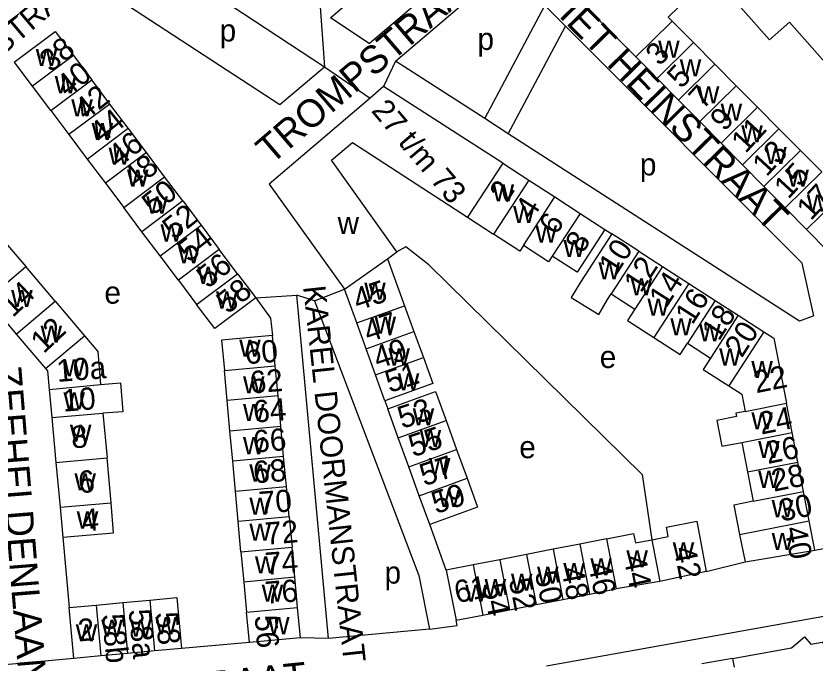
# Model space of a CAD drawing. Extents: x 159902 to 161769, y 383692 to 384875.
# Drawn here: x 160604.7 to 160748.2, y 384500.8 to 384617 of the extents above; entities that cross this region are included whole.
import ezdxf

# ---------------------------------------------------------------- set-up
doc = ezdxf.new("R2010")
doc.units = 0
for name, color, linetype in [('BLT_Basislijn', 7, 'Continuous'), ('BLT_Bebouwing', 7, 'Continuous'), ('BLT_Centroide', 7, 'Continuous'), ('BLT_Huisnummer', 7, 'Continuous'), ('BLT_Huisnummer_ tussenligend', 7, 'Continuous'), ('BLT_Huisnummer_reeks', 7, 'Continuous'), ('BLT_Onderverdeling_panden', 7, 'Continuous'), ('BLT_Straatnaam', 7, 'Continuous'), ('BLT_Straatnaam_verkleind', 7, 'Continuous'), ('BLT_Vlakafsluiter', 7, 'Continuous')]:
    doc.layers.add(name, color=color, linetype=linetype)

msp = doc.modelspace()

# ---------------------------------------------------------------- linework, layer by layer
at = {"layer": 'BLT_Basislijn'}
for p, q in [((160618.79, 384635.3), (160660.13, 384607.85)), ((160661.2, 384616.69), (160683.14, 384635.37)), ((160672.92, 384608.87), (160692.81, 384625.83)), ((160688.92, 384598.57), (160699.73, 384618.89)), ((160703.43, 384615.19), (160699.73, 384618.89)), ((160716.03, 384609.65), (160706.66, 384619.03)), ((160668.17, 384612.03), (160661.2, 384616.69)), ((160693.14, 384595.85), (160703.43, 384615.19)), ((160693.14, 384595.85), (160688.92, 384598.57)), ((160710.48, 384578.65), (160711.75, 384577.86)), ((160660.84, 384505.16), (160655.17, 384566.86)), ((160658.36, 384565.8), (160655.17, 384566.86)), ((160658.36, 384565.8), (160677.11, 384516.47)), ((160670.99, 384547.86), (160671.51, 384546.42)), ((160682.01, 384517.43), (160679.05, 384525.64)), ((160613.15, 384523.37), (160614.29, 384510.72)), ((160748.21, 384521.03), (160760.62, 384523.48)), ((160728.65, 384517.2), (160735.65, 384518.91)), ((160677.11, 384516.47), (160678.99, 384506.84)), ((160678.99, 384506.84), (160660.84, 384505.16)), ((160660.84, 384505.16), (160655.81, 384505.3)), ((160646.65, 384504.46), (160634.45, 384503.37))]:
    msp.add_line(p, q, dxfattribs=at)
for points in [[(160668.17, 384612.03), (160688.35, 384629.26)], [(160615.34, 384625.16), (160652.13, 384601.1), (160660.13, 384607.85)], [(160729.7, 384624.45), (160721.84, 384616.77), (160722.55, 384616.08)], [(160765.29, 384591.35), (160743.62, 384615.9), (160740.04, 384612.73), (160729.7, 384624.45)], [(160605.23, 384617.31), (160592.52, 384607.87), (160575.73, 384593.91)], [(160748.03, 384563.1), (160745.94, 384572.6), (160703.43, 384615.19)], [(160688.92, 384598.57), (160672.92, 384608.87)], [(160748.03, 384563.1), (160745.44, 384562.19), (160693.14, 384595.85)], [(160678.89, 384572.28), (160674.74, 384575.55), (160673.14, 384574.65)], [(160678.89, 384572.28), (160717.16, 384534.63), (160718.93, 384522.9)], [(160647.79, 384566.35), (160650.43, 384562.73), (160650.81, 384559.59)], [(160758.87, 384500), (160751.1, 384509.34), (160700, 384500.18)], [(160678.99, 384506.84), (160683.97, 384507.47), (160683.77, 384508.44)]]:
    msp.add_lwpolyline(points, dxfattribs=at)
at = {"layer": 'BLT_Bebouwing'}
for p, q in [((160722.55, 384616.08), (160719.09, 384612.66)), ((160726.38, 384612.22), (160722.55, 384616.08)), ((160611.79, 384614.23), (160615.06, 384609.88)), ((160719.09, 384612.66), (160716.03, 384609.65)), ((160730.22, 384608.34), (160726.38, 384612.22)), ((160615.06, 384609.88), (160618.34, 384605.53)), ((160607.72, 384604.36), (160604.61, 384608.5)), ((160716.03, 384609.65), (160719.86, 384605.77)), ((160734.07, 384604.47), (160730.22, 384608.34)), ((160621.61, 384601.18), (160618.34, 384605.53)), ((160719.86, 384605.77), (160723.7, 384601.89)), ((160611, 384600.01), (160607.72, 384604.36)), ((160670.75, 384604.32), (160668.34, 384602.26)), ((160692.14, 384590.55), (160670.75, 384604.32)), ((160737.91, 384600.6), (160734.07, 384604.47)), ((160624.88, 384596.82), (160621.61, 384601.18)), ((160668.34, 384602.26), (160650.23, 384586.8)), ((160723.7, 384601.89), (160727.53, 384598.01)), ((160611, 384600.01), (160614.24, 384595.69)), ((160741.75, 384596.73), (160737.91, 384600.6)), ((160628.16, 384592.47), (160624.88, 384596.82)), ((160727.53, 384598.01), (160731.37, 384594.13)), ((160614.24, 384595.69), (160617.54, 384591.3)), ((160745.59, 384592.85), (160741.75, 384596.73)), ((160731.37, 384594.13), (160735.21, 384590.26)), ((160749.43, 384588.98), (160745.59, 384592.85)), ((160617.54, 384591.3), (160620.82, 384586.95)), ((160631.43, 384588.12), (160628.16, 384592.47)), ((160692.14, 384590.55), (160696.81, 384587.52)), ((160735.21, 384590.26), (160739.04, 384586.38)), ((160620.82, 384586.95), (160624.09, 384582.6)), ((160634.7, 384583.76), (160631.43, 384588.12)), ((160650.23, 384586.8), (160663.73, 384567.92)), ((160696.81, 384587.52), (160701.49, 384584.48)), ((160739.04, 384586.38), (160742.88, 384582.5)), ((160701.49, 384584.48), (160706.03, 384581.54)), ((160627.37, 384578.24), (160624.09, 384582.6)), ((160634.7, 384583.76), (160637.98, 384579.41)), ((160742.88, 384582.5), (160746.71, 384578.62)), ((160685.83, 384580.84), (160690.51, 384577.8)), ((160630.64, 384573.89), (160627.37, 384578.24)), ((160637.98, 384579.41), (160641.25, 384575.06)), ((160746.71, 384578.62), (160750.55, 384574.74)), ((160716.57, 384574.76), (160711.75, 384577.86)), ((160603.24, 384575.84), (160606.51, 384571.97)), ((160633.91, 384569.54), (160630.64, 384573.89)), ((160644.52, 384570.7), (160641.25, 384575.06)), ((160716.57, 384574.76), (160720.83, 384572.01)), ((160611.8, 384565.75), (160606.51, 384571.97)), ((160720.83, 384572.01), (160725.55, 384568.96)), ((160644.52, 384570.7), (160647.79, 384566.35)), ((160633.91, 384569.54), (160637.19, 384565.18)), ((160725.55, 384568.96), (160730.27, 384565.91)), ((160611.8, 384565.75), (160617.07, 384559.56)), ((160730.27, 384565.91), (160734.42, 384563.23)), ((160674.52, 384564.95), (160676.21, 384560.29)), ((160734.42, 384563.23), (160739.02, 384560.26)), ((160602.74, 384562.26), (160604.79, 384559.83)), ((160667.62, 384557.17), (160665.93, 384561.84)), ((160604.79, 384559.83), (160610.05, 384553.64)), ((160651.31, 384554.15), (160650.81, 384559.59)), ((160676.21, 384560.29), (160677.9, 384555.62)), ((160739.02, 384560.26), (160740.82, 384559.11)), ((160725.3, 384558.21), (160729.45, 384555.53)), ((160740.82, 384559.11), (160743.09, 384547.41)), ((160669.31, 384552.51), (160667.62, 384557.17)), ((160651.81, 384548.73), (160651.31, 384554.15)), ((160610.05, 384553.64), (160610.39, 384553.24)), ((160610.39, 384553.24), (160610.7, 384549.87)), ((160642.66, 384547.89), (160642.16, 384553.31)), ((160610.7, 384549.87), (160611.17, 384544.85)), ((160652.31, 384543.3), (160651.81, 384548.73)), ((160643.16, 384542.46), (160642.66, 384547.89)), ((160744.11, 384542.14), (160743.09, 384547.41)), ((160620.37, 384545.62), (160621.1, 384537.64)), ((160673.4, 384541.22), (160671.51, 384546.42)), ((160611.17, 384544.85), (160611.92, 384536.77)), ((160681.99, 384544.34), (160683.87, 384539.14)), ((160643.66, 384537.03), (160643.16, 384542.46)), ((160652.81, 384537.87), (160652.31, 384543.3)), ((160675.28, 384536.02), (160673.4, 384541.22)), ((160745.14, 384536.86), (160744.11, 384542.14)), ((160735.07, 384540.37), (160736.1, 384535.09)), ((160683.87, 384539.14), (160685.76, 384533.94)), ((160611.92, 384536.77), (160612.68, 384528.75)), ((160621.83, 384529.52), (160621.1, 384537.64)), ((160644.15, 384531.6), (160643.66, 384537.03)), ((160653.31, 384532.44), (160652.81, 384537.87)), ((160746.17, 384531.58), (160745.14, 384536.86)), ((160677.17, 384530.82), (160675.28, 384536.02)), ((160736.1, 384535.09), (160737.13, 384529.81)), ((160653.81, 384527.01), (160653.31, 384532.44)), ((160644.65, 384526.17), (160644.15, 384531.6)), ((160747.19, 384526.3), (160746.17, 384531.58)), ((160612.68, 384528.75), (160613.15, 384523.37)), ((160653.81, 384527.01), (160654.31, 384521.58)), ((160645.15, 384520.74), (160644.65, 384526.17)), ((160748.21, 384521.03), (160747.19, 384526.3)), ((160734.68, 384523.85), (160735.65, 384518.91)), ((160710.78, 384523.07), (160705.99, 384522.13)), ((160654.81, 384516.16), (160654.31, 384521.58)), ((160701.19, 384521.19), (160696.4, 384520.25)), ((160705.99, 384522.13), (160701.19, 384521.19)), ((160735.65, 384518.91), (160748.21, 384521.03)), ((160645.15, 384520.74), (160645.65, 384515.31)), ((160696.4, 384520.25), (160691.6, 384519.31)), ((160691.6, 384519.31), (160686.81, 384518.37)), ((160645.65, 384515.31), (160646.15, 384509.89)), ((160655.31, 384510.73), (160654.81, 384516.16)), ((160720.38, 384515.38), (160712.54, 384514.06)), ((160707.75, 384513.12), (160712.54, 384514.06)), ((160698.16, 384511.25), (160702.96, 384512.19)), ((160702.96, 384512.19), (160707.75, 384513.12)), ((160614.29, 384510.72), (160619.12, 384511.17)), ((160619.12, 384511.17), (160623.95, 384511.61)), ((160623.95, 384511.61), (160628.77, 384512.06)), ((160655.81, 384505.3), (160655.31, 384510.73)), ((160693.37, 384510.31), (160698.16, 384511.25)), ((160615.14, 384501.58), (160614.29, 384510.72)), ((160646.65, 384504.46), (160646.15, 384509.89)), ((160688.57, 384509.38), (160693.37, 384510.31)), ((160655.81, 384505.3), (160646.65, 384504.46)), ((160624.8, 384502.47), (160619.97, 384502.03)), ((160629.62, 384502.92), (160624.8, 384502.47)), ((160634.45, 384503.37), (160629.62, 384502.92)), ((160619.97, 384502.03), (160615.14, 384501.58)), ((160733.41, 384501.57), (160727.9, 384500.58))]:
    msp.add_line(p, q, dxfattribs=at)
for points in [[(160604.61, 384608.5), (160604.45, 384608.71), (160611.79, 384614.23)], [(160673.14, 384574.65), (160661.4, 384591.1), (160665.18, 384594.28), (160685.83, 384580.84)], [(160706.03, 384581.54), (160710.48, 384578.65)], [(160710.48, 384578.65), (160705.49, 384570.96), (160701.04, 384573.84)], [(160695.85, 384575.78), (160695.85, 384575.78), (160695.19, 384574.77), (160690.51, 384577.8)], [(160711.75, 384577.86), (160711.75, 384577.86), (160706.13, 384569.15), (160704.45, 384566.42), (160709.38, 384563.38), (160710.94, 384566.04), (160711.59, 384567.05)], [(160701.04, 384573.84), (160700.39, 384572.84), (160695.85, 384575.78)], [(160671.46, 384573.39), (160673.14, 384574.65)], [(160671.46, 384573.39), (160674.52, 384564.95)], [(160665.93, 384561.84), (160663.73, 384567.92)], [(160711.59, 384567.05), (160711.59, 384567.05), (160715.85, 384564.3)], [(160647.79, 384566.35), (160640.46, 384560.83), (160637.19, 384565.18)], [(160715.85, 384564.3), (160714.55, 384562.29), (160719.27, 384559.24)], [(160617.07, 384559.56), (160619.45, 384556.73), (160619.94, 384550.81)], [(160650.81, 384559.59), (160641.66, 384558.74), (160642.16, 384553.31)], [(160719.27, 384559.24), (160723.99, 384556.19), (160725.3, 384558.21)], [(160677.9, 384555.62), (160679.59, 384550.96), (160670.99, 384547.86)], [(160729.45, 384555.53), (160728.15, 384553.51), (160732.75, 384550.54)], [(160670.99, 384547.86), (160669.31, 384552.51)], [(160619.94, 384550.81), (160623.52, 384551.1), (160623.95, 384545.91), (160620.37, 384545.62)], [(160671.51, 384546.42), (160680.1, 384549.54), (160681.99, 384544.34)], [(160732.75, 384550.54), (160735.05, 384549.05), (160735.65, 384545.96)], [(160735.65, 384545.96), (160734.03, 384545.65), (160734.15, 384545.02), (160730.6, 384544.32), (160731.49, 384539.71), (160735.07, 384540.37)], [(160685.76, 384533.94), (160687.64, 384528.74), (160679.05, 384525.64)], [(160679.05, 384525.64), (160677.17, 384530.82)], [(160613.15, 384523.37), (160622.28, 384524.14), (160621.83, 384529.52)], [(160737.13, 384529.81), (160733.65, 384529.13), (160734.68, 384523.85)], [(160718.93, 384522.9), (160721.88, 384523.47), (160721.55, 384525.15), (160721.55, 384525.15), (160726.99, 384526.21), (160728.65, 384517.2)], [(160710.78, 384523.07), (160715.65, 384524.01), (160715.98, 384522.33), (160718.93, 384522.9)], [(160686.81, 384518.37), (160682.01, 384517.43)], [(160682.01, 384517.43), (160683.77, 384508.44)], [(160728.65, 384517.2), (160720.38, 384515.38)], [(160628.77, 384512.06), (160633.6, 384512.51), (160634.45, 384503.37)], [(160683.77, 384508.44), (160688.57, 384509.38)], [(160733.41, 384501.57), (160743.97, 384503.51), (160746.35, 384505.48), (160747.44, 384504.14), (160749.48, 384504.51), (160755.21, 384497.65), (160753.83, 384496.49), (160755.27, 384494.77)]]:
    msp.add_lwpolyline(points, dxfattribs=at)
at = {"layer": 'BLT_Onderverdeling_panden'}
for p, q in [((160726.38, 384612.22), (160719.86, 384605.77)), ((160615.06, 384609.88), (160607.72, 384604.36)), ((160730.22, 384608.34), (160723.7, 384601.89)), ((160611, 384600.01), (160618.34, 384605.53)), ((160734.07, 384604.47), (160727.53, 384598.01)), ((160621.61, 384601.18), (160614.24, 384595.69)), ((160737.91, 384600.6), (160731.37, 384594.13)), ((160617.54, 384591.3), (160624.88, 384596.82)), ((160741.75, 384596.73), (160735.21, 384590.26)), ((160745.59, 384592.85), (160739.04, 384586.38)), ((160628.16, 384592.47), (160620.82, 384586.95)), ((160692.14, 384590.55), (160685.83, 384580.84)), ((160749.43, 384588.98), (160742.88, 384582.5)), ((160624.09, 384582.6), (160631.43, 384588.12)), ((160696.81, 384587.52), (160690.51, 384577.8)), ((160695.85, 384575.78), (160701.49, 384584.48)), ((160753.27, 384585.11), (160746.71, 384578.62)), ((160634.7, 384583.76), (160627.37, 384578.24)), ((160706.03, 384581.54), (160701.04, 384573.84)), ((160630.64, 384573.89), (160637.98, 384579.41)), ((160641.25, 384575.06), (160633.91, 384569.54)), ((160716.57, 384574.76), (160711.59, 384567.05)), ((160599.49, 384566.03), (160606.51, 384571.97)), ((160720.83, 384572.01), (160715.85, 384564.3)), ((160637.19, 384565.18), (160644.52, 384570.7)), ((160725.55, 384568.96), (160719.27, 384559.24)), ((160604.79, 384559.83), (160611.8, 384565.75)), ((160730.27, 384565.91), (160725.3, 384558.21)), ((160665.93, 384561.84), (160674.52, 384564.95)), ((160734.42, 384563.23), (160729.45, 384555.53)), ((160610.05, 384553.64), (160617.07, 384559.56)), ((160667.62, 384557.17), (160676.21, 384560.29)), ((160739.02, 384560.26), (160732.75, 384550.54)), ((160669.31, 384552.51), (160677.9, 384555.62)), ((160642.16, 384553.31), (160651.31, 384554.15)), ((160610.7, 384549.87), (160619.94, 384550.81)), ((160651.81, 384548.73), (160642.66, 384547.89)), ((160735.65, 384545.96), (160743.09, 384547.41)), ((160611.17, 384544.85), (160620.37, 384545.62)), ((160673.4, 384541.22), (160681.99, 384544.34)), ((160643.16, 384542.46), (160652.31, 384543.3)), ((160735.07, 384540.37), (160744.11, 384542.14)), ((160675.28, 384536.02), (160683.87, 384539.14)), ((160611.92, 384536.77), (160621.1, 384537.64)), ((160652.81, 384537.87), (160643.66, 384537.03)), ((160736.1, 384535.09), (160745.14, 384536.86)), ((160677.17, 384530.82), (160685.76, 384533.94)), ((160644.15, 384531.6), (160653.31, 384532.44)), ((160737.13, 384529.81), (160746.17, 384531.58)), ((160612.68, 384528.75), (160621.83, 384529.52)), ((160653.81, 384527.01), (160644.65, 384526.17)), ((160734.68, 384523.85), (160747.19, 384526.3)), ((160710.78, 384523.07), (160712.54, 384514.06)), ((160718.93, 384522.9), (160720.38, 384515.38)), ((160645.15, 384520.74), (160654.31, 384521.58)), ((160701.19, 384521.19), (160702.96, 384512.19)), ((160705.99, 384522.13), (160707.75, 384513.12)), ((160696.4, 384520.25), (160698.16, 384511.25)), ((160686.81, 384518.37), (160688.57, 384509.38)), ((160691.6, 384519.31), (160693.37, 384510.31)), ((160654.81, 384516.16), (160645.65, 384515.31)), ((160619.12, 384511.17), (160619.97, 384502.03)), ((160623.95, 384511.61), (160624.8, 384502.47)), ((160628.77, 384512.06), (160629.62, 384502.92)), ((160646.15, 384509.89), (160655.31, 384510.73)), ((160733.41, 384501.57), (160733.7, 384500))]:
    msp.add_line(p, q, dxfattribs=at)
msp.add_lwpolyline([(160663.73, 384567.92), (160671.46, 384573.39)], dxfattribs=at)
at = {"layer": 'BLT_Vlakafsluiter'}
for p, q in [((160659.17, 384621.54), (160660.13, 384607.85)), ((160672.92, 384608.87), (160670.75, 384604.32)), ((160660.13, 384607.85), (160668.34, 384602.26)), ((160647.79, 384566.35), (160655.17, 384566.86)), ((160658.36, 384565.8), (160663.73, 384567.92)), ((160615.14, 384501.58), (160600.21, 384500.22))]:
    msp.add_line(p, q, dxfattribs=at)

# ---------------------------------------------------------------- texts
at = {"layer": 'BLT_Centroide'}
for s, p in [('p', (160641.31, 384612.41)), ('p', (160687.61, 384610.89)), ('w', (160720.05, 384609.5)), ('w', (160608.3, 384607.99)), ('w', (160723.93, 384606.13)), ('w', (160611.71, 384603.12)), ('w', (160727.18, 384601.29)), ('w', (160614.68, 384598.94)), ('w', (160731.27, 384598.18)), ('w', (160618.33, 384594.7)), ('w', (160734.98, 384594.28)), ('w', (160621.38, 384590.28)), ('w', (160739.27, 384590.38)), ('p', (160716.77, 384588.35)), ('w', (160624.68, 384586.33)), ('w', (160743.25, 384586.32)), ('w', (160690.32, 384583.67)), ('w', (160628.15, 384581.5)), ('w', (160746.74, 384581.84)), ('w', (160694.01, 384579.81)), ('w', (160662.49, 384577.82)), ('w', (160630.7, 384576.48)), ('w', (160698.03, 384576.29)), ('w', (160703.05, 384573.69)), ('w', (160633.86, 384572.54)), ('w', (160709.34, 384569.67)), ('w', (160637.32, 384568.86)), ('w', (160715.12, 384566.82)), ('e', (160620.62, 384565.31)), ('w', (160667.28, 384566.03)), ('w', (160603.87, 384564.72)), ('w', (160640.67, 384564.43)), ('w', (160718.13, 384563.13)), ('w', (160669.13, 384559.91)), ('w', (160722.24, 384559.61)), ('w', (160609.16, 384558.31)), ('w', (160727.4, 384558.56)), ('w', (160644.83, 384555.8)), ('w', (160671.61, 384554.2)), ('e', (160709.56, 384553.75)), ('w', (160731.01, 384554.2)), ('w', (160613.27, 384552.27)), ('w', (160736.78, 384551.93)), ('w', (160673.3, 384549.74)), ('w', (160645.51, 384549.21)), ('w', (160613.27, 384546.33)), ('w', (160645.51, 384544.22)), ('w', (160675.98, 384543.44)), ('w', (160736.78, 384542.74)), ('w', (160614.43, 384540.5)), ('w', (160677.23, 384539.57)), ('w', (160645.51, 384538.27)), ('e', (160695.11, 384537.55)), ('w', (160738, 384537.59)), ('w', (160678.9, 384534.54)), ('w', (160646.65, 384533.35)), ('w', (160738, 384532.22)), ('w', (160615.24, 384531.76)), ('w', (160680.58, 384528.76)), ('w', (160646.65, 384527.4)), ('w', (160740.43, 384526.94)), ('w', (160615.65, 384524.91)), ('w', (160646.65, 384522.72)), ('w', (160740.43, 384521.07)), ('w', (160722.67, 384519.36)), ('w', (160714.35, 384517.92)), ('w', (160647.65, 384516.86)), ('w', (160707.87, 384516.52)), ('p', (160670.92, 384515.02)), ('w', (160698.3, 384515)), ('w', (160703.02, 384515.66)), ('w', (160693.62, 384513.73)), ('w', (160688.89, 384512.75)), ('w', (160648.87, 384511.77)), ('w', (160685.41, 384511.78)), ('w', (160620.05, 384505.48)), ('w', (160625.22, 384505.48)), ('w', (160629.76, 384505.93)), ('w', (160650, 384505.93)), ('w', (160615.48, 384504.63))]:
    msp.add_text(s, height=4, dxfattribs=at).set_placement(p)
at = {"layer": 'BLT_Huisnummer'}
for s, rotation, p in [('38', 38.5028, (160611, 384606.72)), ('3', 47.3931, (160720.35, 384607.85)), ('42', 38.5028, (160617.25, 384598.09)), ('7', 47.3931, (160728.1, 384600.05)), ('11', 47.3931, (160735.74, 384592.16)), ('46', 38.5028, (160623.3, 384589.73)), ('15', 47.3931, (160743.42, 384583.94)), ('50', 38.5028, (160629.38, 384581.05)), ('2', 57.3931, (160692.86, 384583.29)), ('6', 57.3931, (160701.73, 384577.46)), ('54', 38.5028, (160635.8, 384572.58)), ('10', 57.3931, (160712.48, 384570.22)), ('14', 57.3931, (160721.5, 384564.38)), ('58', 38.5028, (160642.76, 384563.33)), ('14', 43.5028, (160604.18, 384562.72)), ('45', 18.3931, (160666.09, 384564.01)), ('47', 18.3931, (160667.99, 384558.31)), ('18', 57.3931, (160730.96, 384558.44)), ('60', 4.5028, (160645.98, 384554.42)), ('10a', 4.5028, (160612.17, 384551.24)), ('51', 18.3931, (160671.83, 384549.25)), ('22', 11.3931, (160737.64, 384549.21)), ('64', 4.5028, (160647.5, 384543.92)), ('8', 4.5028, (160614.79, 384539.3)), ('55', 18.3931, (160676.04, 384537.7)), ('26', 11.3931, (160739.74, 384536.5)), ('68', 4.5028, (160647.5, 384533.01)), ('59', 18.3931, (160680.16, 384527.49)), ('30', 11.3931, (160742.17, 384526.14)), ('4', 4.5028, (160616.79, 384524.36)), ('72', 4.5028, (160649.63, 384522)), ('40', 281.3931, (160742.69, 384524.95)), ('42', 281.3931, (160722.81, 384521.34)), ('46', 281.3931, (160707.47, 384518.5)), ('50', 281.3931, (160697.9, 384516.98)), ('76', 4.5028, (160649.6, 384511.37)), ('61', 11.3931, (160683.89, 384511.48)), ('54', 281.3931, (160688.49, 384514.73)), ('58b', 275.5028, (160620.17, 384509.44)), ('58a', 275.5028, (160624.96, 384510.29)), ('58', 275.5028, (160629.78, 384509.77)), ('2', 5.5028, (160616.06, 384504.61)), ('56', 274.5028, (160647.61, 384509.23))]:
    msp.add_text(s, height=4, rotation=rotation, dxfattribs=at).set_placement(p)
at = {"layer": 'BLT_Huisnummer_ tussenligend'}
for s, rotation, p in [('40', 38.5028, (160613.97, 384602.28)), ('5', 47.3931, (160724.22, 384603.78)), ('44', 38.5028, (160619.98, 384593.82)), ('9', 47.3931, (160731.94, 384596.1)), ('13', 47.3931, (160739.52, 384587.97)), ('48', 38.5028, (160626, 384585.66)), ('17', 47.3931, (160747.48, 384580.09)), ('4', 57.3931, (160697.47, 384580.29)), ('52', 38.5028, (160633.07, 384576.68)), ('8', 57.3931, (160706.47, 384574.17)), ('56', 38.5028, (160639.19, 384567.9)), ('12', 57.3931, (160716.97, 384567.08)), ('16', 57.3931, (160726.19, 384561.35)), ('12', 43.5028, (160609.71, 384556.2)), ('20', 57.3931, (160735.08, 384555.44)), ('49', 18.3931, (160669.71, 384553.56)), ('62', 4.5028, (160646.88, 384549.17)), ('10', 4.5028, (160613.27, 384545.9)), ('53', 18.3931, (160674.08, 384542.8)), ('24', 11.3931, (160738.56, 384541.78)), ('66', 4.5028, (160647.49, 384538.54)), ('57', 18.3931, (160678.04, 384532.49)), ('6', 4.5028, (160616.08, 384531.25)), ('28', 11.3931, (160740.83, 384531.52)), ('70', 4.5028, (160648.49, 384527.53)), ('74', 4.5028, (160649.61, 384516.58)), ('44', 281.3931, (160713.82, 384519.76)), ('48', 281.3931, (160702.63, 384517.63)), ('52', 281.3931, (160693.22, 384515.69))]:
    msp.add_text(s, height=4, rotation=rotation, dxfattribs=at).set_placement(p)
at = {"layer": 'BLT_Huisnummer_reeks'}
msp.add_text('27 t/m 73', height=4, rotation=310.3931, dxfattribs=at).set_placement((160668.4, 384599.92))
at = {"layer": 'BLT_Straatnaam'}
for s, rotation, p in [('TROMPSTRAAT', 40.5647, (160650.59, 384590.18)), ('PIET HEINSTRAAT', 314.3958, (160698.94, 384620.17)), ('ZEEHELDENLAAN', 274.6244, (160600.69, 384553.95)), ('VAN KINSBERGENSTRAAT', 5.8321, (160571.74, 384487.28))]:
    msp.add_text(s, height=5, rotation=rotation, dxfattribs=at).set_placement(p)
at = {"layer": 'BLT_Straatnaam_verkleind'}
for s, rotation, p in [('BARBAROSSTRAAT', 40.1608, (160579.56, 384590.63)), ('KAREL DOORMANSTRAAT', 276.1608, (160656.29, 384568.37))]:
    msp.add_text(s, height=4, rotation=rotation, dxfattribs=at).set_placement(p)

doc.saveas('drawing.dxf')
